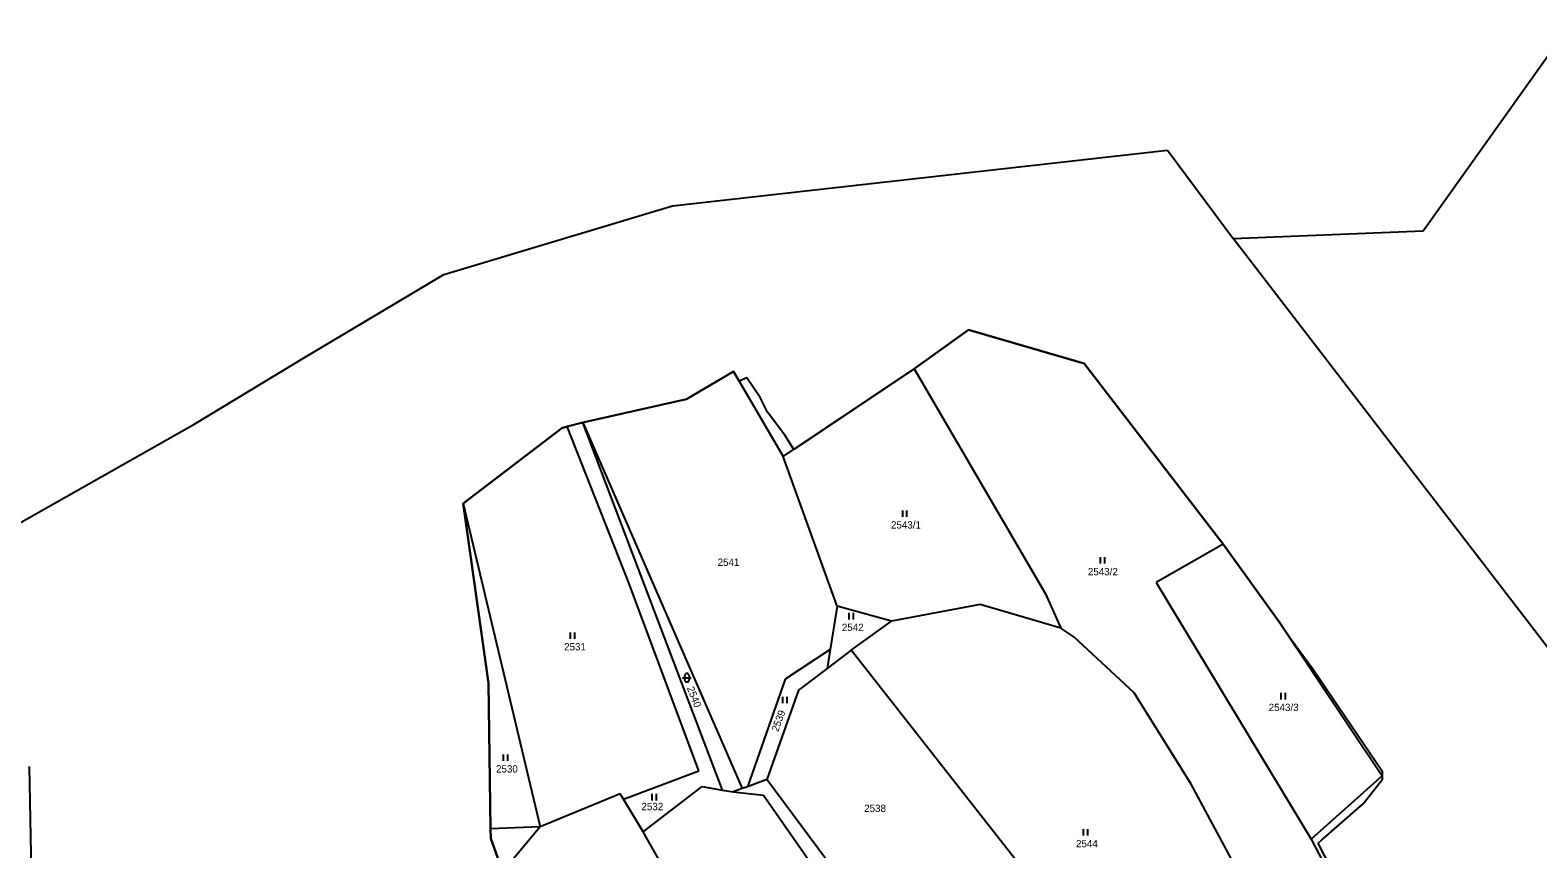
# Model space of a CAD drawing. Extents: x -439246 to -433691, y -1130252 to -1121148.
# Drawn here: x -435352.8 to -435002.8, y -1128550 to -1128360 of the extents above; entities that cross this region are included whole.
import ezdxf

# ---------------------------------------------------------------- set-up
doc = ezdxf.new("R2010")
doc.units = 0
for name, color, linetype in [('Vrstva 1', 7, 'Continuous'), ('Vrstva 18', 7, 'Continuous'), ('Vrstva 25', 7, 'Continuous'), ('Vrstva 52', 7, 'Continuous')]:
    doc.layers.add(name, color=color, linetype=linetype)

msp = doc.modelspace()

# ---------------------------------------------------------------- linework, layer by layer
at = {"layer": 'Vrstva 1'}
for points in [[(-435029.41, -1128406.55), (-434996.16, -1128359.98)], [(-435203.67, -1128400.77), (-435088.77, -1128387.85)], [(-435088.77, -1128387.85), (-435073.5, -1128408.29)], [(-435256.73, -1128416.68), (-435203.67, -1128400.77)], [(-435073.5, -1128408.29), (-435029.41, -1128406.55)], [(-435009.37, -1128491.73), (-435073.5, -1128408.29)], [(-435289.14, -1128435.92), (-435256.73, -1128416.68)], [(-435147.53, -1128438.56), (-435134.93, -1128429.55)], [(-435134.93, -1128429.55), (-435108.07, -1128437.33)], [(-435314.59, -1128451.37), (-435289.14, -1128435.92)], [(-435200.45, -1128445.62), (-435189.49, -1128439.21)], [(-435189.49, -1128439.21), (-435177.95, -1128458.95)], [(-435177.95, -1128458.95), (-435147.53, -1128438.56)], [(-435147.53, -1128438.56), (-435117.07, -1128490.78)], [(-435108.07, -1128437.33), (-435075.82, -1128479.24)], [(-435224.49, -1128451.04), (-435200.45, -1128445.62)], [(-435363.71, -1128479.13), (-435314.59, -1128451.37)], [(-435252.28, -1128469.84), (-435229.39, -1128452.31)], [(-435229.39, -1128452.31), (-435228.14, -1128451.98)], [(-435228.14, -1128451.98), (-435224.49, -1128451.04)], [(-435213.82, -1128488.2), (-435228.14, -1128451.98)], [(-435192.04, -1128536.33), (-435224.49, -1128451.04)], [(-435224.49, -1128451.04), (-435187.51, -1128535.99)], [(-435165.41, -1128493.68), (-435177.95, -1128458.95)], [(-435252.28, -1128469.84), (-435234.42, -1128544.88)], [(-435246.39, -1128511.52), (-435252.28, -1128469.84)], [(-435075.82, -1128479.24), (-435091.41, -1128488.18)], [(-435075.82, -1128479.24), (-435062.7, -1128497.55)], [(-435197.52, -1128531.86), (-435213.82, -1128488.2)], [(-435091.41, -1128488.18), (-435055.43, -1128547.75)], [(-435117.07, -1128490.78), (-435113.5, -1128498.73)], [(-434944.65, -1128575.95), (-435009.37, -1128491.73)], [(-435165.41, -1128493.68), (-435167.04, -1128503.68)], [(-435152.8, -1128497.11), (-435165.41, -1128493.68)], [(-435132.25, -1128493.24), (-435152.8, -1128497.11)], [(-435113.5, -1128498.73), (-435132.25, -1128493.24)], [(-435162.2, -1128503.89), (-435152.8, -1128497.11)], [(-435110.53, -1128500.77), (-435113.5, -1128498.73)], [(-435062.7, -1128497.55), (-435038.92, -1128533.02)], [(-435096.46, -1128513.74), (-435110.53, -1128500.77)], [(-435167.04, -1128503.68), (-435177.48, -1128510.61)], [(-435167.04, -1128503.68), (-435167.75, -1128508.08)], [(-435162.2, -1128503.89), (-435167.75, -1128508.08)], [(-435121.29, -1128555.9), (-435162.2, -1128503.89)], [(-435167.75, -1128508.08), (-435174.4, -1128513.1)], [(-435245.91, -1128545.29), (-435246.39, -1128511.52)], [(-435177.48, -1128510.61), (-435186.28, -1128535.54)], [(-435174.4, -1128513.1), (-435181.76, -1128533.88)], [(-435083.26, -1128534.96), (-435096.46, -1128513.74)], [(-435353.05, -1128530.85), (-435352.55, -1128555.22)], [(-435215.07, -1128538.41), (-435197.52, -1128531.86)], [(-435038.92, -1128533.02), (-435055.43, -1128547.75)], [(-435215.81, -1128537.17), (-435234.42, -1128544.88)], [(-435215.07, -1128538.41), (-435215.81, -1128537.17)], [(-435210.48, -1128546.03), (-435196.77, -1128535.51)], [(-435196.77, -1128535.51), (-435192.04, -1128536.33)], [(-435192.04, -1128536.33), (-435189.58, -1128536.76)], [(-435187.51, -1128535.99), (-435189.58, -1128536.76)], [(-435189.58, -1128536.76), (-435182.52, -1128537.48)], [(-435186.28, -1128535.54), (-435187.51, -1128535.99)], [(-435181.76, -1128533.88), (-435186.28, -1128535.54)], [(-435154.08, -1128571.15), (-435181.76, -1128533.88)], [(-435055.79, -1128586.01), (-435083.26, -1128534.96)], [(-435210.48, -1128546.03), (-435215.07, -1128538.41)], [(-435182.52, -1128537.48), (-435158.8, -1128571.51)], [(-435234.42, -1128544.88), (-435245.91, -1128545.29)], [(-435245.87, -1128547.54), (-435245.91, -1128545.29)], [(-435224.71, -1128606.74), (-435245.87, -1128547.54)], [(-435234.42, -1128544.88), (-435241.45, -1128553.28)], [(-435191.33, -1128579.77), (-435210.48, -1128546.03)], [(-435055.43, -1128547.75), (-435039.99, -1128577.17)]]:
    msp.add_lwpolyline(points, dxfattribs=at)
at = {"layer": 'Vrstva 25'}
for p, q in [((-435150.23, -1128472.93), (-435150.23, -1128471.43)), ((-435149.23, -1128472.93), (-435149.23, -1128471.43)), ((-435104.29, -1128483.78), (-435104.29, -1128482.28)), ((-435103.29, -1128483.78), (-435103.29, -1128482.28)), ((-435162.64, -1128496.71), (-435162.64, -1128495.21)), ((-435161.64, -1128496.71), (-435161.64, -1128495.21)), ((-435227.36, -1128501.22), (-435227.36, -1128499.72)), ((-435226.36, -1128501.22), (-435226.36, -1128499.72)), ((-435201.33, -1128510.24), (-435199.33, -1128510.24)), ((-435200.83, -1128510.74), (-435200.83, -1128509.74)), ((-435199.83, -1128509.74), (-435199.83, -1128510.74)), ((-435178.02, -1128516.18), (-435178.02, -1128514.68)), ((-435177.02, -1128516.18), (-435177.02, -1128514.68)), ((-435062.32, -1128515.28), (-435062.32, -1128513.78)), ((-435061.32, -1128515.28), (-435061.32, -1128513.78)), ((-435242.87, -1128529.55), (-435242.87, -1128528.05)), ((-435241.87, -1128529.55), (-435241.87, -1128528.05)), ((-435208.37, -1128538.72), (-435208.37, -1128537.22)), ((-435207.37, -1128538.72), (-435207.37, -1128537.22)), ((-435108.27, -1128546.89), (-435108.27, -1128545.39)), ((-435107.27, -1128546.89), (-435107.27, -1128545.39))]:
    msp.add_line(p, q, dxfattribs=at)
for centre, start, end in [((-435200.33, -1128509.74), 0, 180), ((-435200.33, -1128510.74), 180, 0)]:
    msp.add_arc(centre, 0.5, start, end, dxfattribs=at)
at = {"layer": 'Vrstva 52'}
for points in [[(-435108.07, -1128437.33), (-435134.93, -1128429.55), (-435147.53, -1128438.56)], [(-435147.53, -1128438.56), (-435175.52, -1128457.32), (-435177.6, -1128453.96), (-435181.64, -1128448.64), (-435183.34, -1128445.24), (-435186.4, -1128440.67), (-435188.18, -1128441.44), (-435189.49, -1128439.21), (-435200.45, -1128445.62), (-435224.49, -1128451.04), (-435228.14, -1128451.98), (-435229.39, -1128452.31), (-435252.28, -1128469.84), (-435246.39, -1128511.52), (-435245.91, -1128545.29), (-435245.87, -1128547.54), (-435224.71, -1128606.74)], [(-435027.8, -1128599.24), (-435053.76, -1128548.66), (-435052.89, -1128547.9), (-435051.82, -1128546.97), (-435043.31, -1128539.52), (-435038.84, -1128533.77), (-435038.84, -1128532.07), (-435055.01, -1128508.23), (-435060.22, -1128501.24), (-435062.7, -1128497.55), (-435075.82, -1128479.24), (-435108.07, -1128437.33)]]:
    msp.add_lwpolyline(points, dxfattribs=at)

# ---------------------------------------------------------------- texts
at = {"layer": 'Vrstva 18'}
for s, p in [('2543/1', (-435152.94, -1128475.63)), ('2541', (-435193.19, -1128484.3)), ('2543/2', (-435107.23, -1128486.48)), ('2542', (-435164.34, -1128499.41)), ('2531', (-435228.83, -1128503.92)), ('2543/3', (-435065.26, -1128517.98)), ('2530', (-435244.64, -1128532.25)), ('2532', (-435210.88, -1128540.99)), ('2538', (-435159.17, -1128541.4)), ('2544', (-435109.98, -1128549.59))]:
    msp.add_text(s, height=1.7, dxfattribs=at).set_placement(p)
for s, rotation, p in [('2540', 291.5401, (-435200.35, -1128512.65)), ('2539', 69.7421, (-435179.15, -1128522.9))]:
    msp.add_text(s, height=1.7, rotation=rotation, dxfattribs=at).set_placement(p)

doc.saveas('drawing.dxf')
